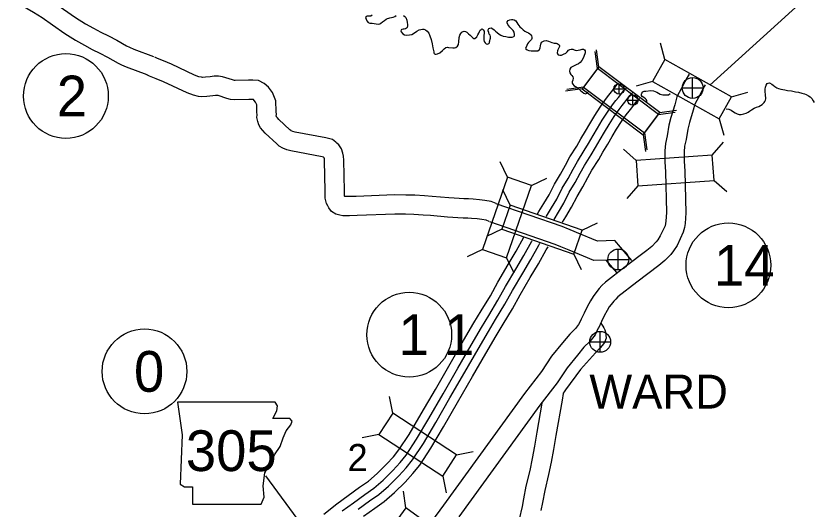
# Model space of a CAD drawing. Extents: x 1367863 to 1368197, y 380048 to 380261.
# Drawn here: x 1367891.07 to 1367912.71, y 380229.6 to 380242.97 of the extents above; entities that cross this region are included whole.
import ezdxf

# ---------------------------------------------------------------- set-up
doc = ezdxf.new("R2010")
doc.units = 0
for name, color, linetype in [('Level 10', 7, 'Continuous'), ('Level 15', 7, 'Continuous'), ('Level 2', 7, 'Continuous'), ('Level 20', 7, 'Continuous'), ('Level 21', 7, 'Continuous'), ('Level 26', 7, 'Continuous'), ('Level 27', 7, 'Continuous'), ('Level 30', 7, 'Continuous'), ('Level 6', 7, 'Continuous')]:
    doc.layers.add(name, color=color, linetype=linetype)

msp = doc.modelspace()

# ---------------------------------------------------------------- linework, layer by layer
at = {"layer": 'Level 10'}
for points in [[(1367891.032, 380243.854), (1367891.22, 380243.794), (1367891.456, 380243.711), (1367891.621, 380243.63), (1367891.816, 380243.521), (1367892.075, 380243.361), (1367892.365, 380243.153), (1367892.691, 380242.923), (1367892.954, 380242.757), (1367893.176, 380242.635), (1367893.378, 380242.527), (1367893.584, 380242.429), (1367893.807, 380242.311), (1367894.073, 380242.155), (1367894.149, 380242.124), (1367894.269, 380242.066), (1367894.803, 380241.868)], [(1367891.055, 380243.298), (1367891.254, 380243.229), (1367891.378, 380243.168), (1367891.551, 380243.071), (1367891.785, 380242.926), (1367892.062, 380242.728), (1367892.4, 380242.488), (1367892.689, 380242.307), (1367892.927, 380242.176), (1367893.142, 380242.061), (1367893.349, 380241.962), (1367893.553, 380241.854), (1367893.842, 380241.684), (1367893.938, 380241.646), (1367894.062, 380241.585), (1367894.621, 380241.378)], [(1367896.104, 380241.306), (1367896.03, 380241.321), (1367895.915, 380241.364), (1367895.289, 380241.659), (1367895.072, 380241.751), (1367894.912, 380241.811), (1367894.837, 380241.852)], [(1367896.024, 380240.789), (1367895.885, 380240.818), (1367895.713, 380240.881), (1367895.075, 380241.182), (1367894.878, 380241.266), (1367894.694, 380241.335), (1367894.587, 380241.393)], [(1367904.091, 380237.885), (1367903.96, 380237.935), (1367903.788, 380237.965), (1367903.64, 380237.985), (1367903.468, 380238.002), (1367903.34, 380238.009), (1367903.218, 380238.01), (1367903.087, 380238.017), (1367902.954, 380238.026), (1367902.811, 380238.037), (1367902.354, 380238.075), (1367902.15, 380238.092), (1367901.885, 380238.11), (1367901.646, 380238.114), (1367901.339, 380238.117), (1367900.301, 380238.077), (1367900.115, 380238.07), (1367900.022, 380238.071), (1367899.986, 380238.072), (1367899.979, 380238.084), (1367899.978, 380238.09), (1367899.979, 380238.228), (1367899.961, 380239.061), (1367899.957, 380239.164), (1367899.939, 380239.253), (1367899.903, 380239.366), (1367899.828, 380239.477), (1367899.776, 380239.52), (1367899.749, 380239.547), (1367899.652, 380239.623), (1367899.477, 380239.663), (1367898.64, 380239.821), (1367898.578, 380239.837), (1367898.539, 380239.853), (1367898.523, 380239.862), (1367898.498, 380239.885), (1367898.199, 380240.164), (1367898.16, 380240.205), (1367898.139, 380240.23), (1367898.134, 380240.245), (1367898.132, 380240.255), (1367898.134, 380240.299), (1367898.128, 380240.38), (1367898.121, 380240.671), (1367898.029, 380240.891), (1367897.923, 380241.035), (1367897.804, 380241.141), (1367897.652, 380241.215), (1367897.494, 380241.229), (1367897.377, 380241.227), (1367897.016, 380241.214), (1367896.995, 380241.216), (1367896.944, 380241.232), (1367896.669, 380241.321), (1367896.567, 380241.335), (1367896.444, 380241.338), (1367896.338, 380241.321), (1367896.209, 380241.306), (1367896.13, 380241.303), (1367896.104, 380241.306)], [(1367909.178, 380241.111), (1367909.257, 380241.253), (1367909.337, 380241.391)], [(1367909.176, 380241.108), (1367908.997, 380240.777), (1367908.935, 380240.563), (1367908.833, 380240.219), (1367908.779, 380240.007), (1367908.73, 380239.721), (1367908.684, 380239.511), (1367908.668, 380239.308), (1367908.668, 380239.017), (1367908.688, 380238.74), (1367908.712, 380237.64), (1367908.705, 380237.523), (1367908.698, 380237.403), (1367908.688, 380237.341), (1367908.672, 380237.275), (1367908.615, 380237.149), (1367908.544, 380237.006), (1367908.476, 380236.901), (1367908.432, 380236.843), (1367908.315, 380236.721), (1367908.181, 380236.611), (1367907.593, 380236.17), (1367907.055, 380235.749), (1367906.963, 380235.662), (1367906.89, 380235.583), (1367906.794, 380235.467), (1367906.723, 380235.367), (1367906.65, 380235.245), (1367906.562, 380235.08), (1367906.477, 380234.91), (1367906.393, 380234.732)], [(1367909.634, 380240.856), (1367909.711, 380240.994), (1367909.773, 380241.102)], [(1367909.635, 380240.86), (1367909.483, 380240.578), (1367909.437, 380240.417), (1367909.337, 380240.08), (1367909.29, 380239.898), (1367909.243, 380239.621), (1367909.202, 380239.434), (1367909.19, 380239.288), (1367909.19, 380239.035), (1367909.209, 380238.764), (1367909.235, 380237.629), (1367909.226, 380237.491), (1367909.218, 380237.345), (1367909.2, 380237.236), (1367909.168, 380237.105), (1367909.087, 380236.925), (1367908.998, 380236.747), (1367908.904, 380236.601), (1367908.829, 380236.503), (1367908.67, 380236.337), (1367908.503, 380236.2), (1367907.911, 380235.756), (1367907.397, 380235.353), (1367907.335, 380235.294), (1367907.282, 380235.238), (1367907.208, 380235.148), (1367907.161, 380235.081), (1367907.105, 380234.988), (1367907.026, 380234.839), (1367906.947, 380234.682), (1367906.866, 380234.51)], [(1367903.905, 380237.397), (1367903.82, 380237.429), (1367903.708, 380237.449), (1367903.581, 380237.466), (1367903.429, 380237.481), (1367903.324, 380237.487), (1367903.202, 380237.488), (1367903.054, 380237.496), (1367902.916, 380237.505), (1367902.77, 380237.517), (1367902.31, 380237.555), (1367902.11, 380237.571), (1367901.863, 380237.588), (1367901.639, 380237.592), (1367901.347, 380237.595), (1367900.321, 380237.555), (1367900.121, 380237.547), (1367900.015, 380237.549), (1367899.935, 380237.55), (1367899.853, 380237.566), (1367899.745, 380237.595), (1367899.627, 380237.671), (1367899.553, 380237.765), (1367899.529, 380237.818), (1367899.491, 380237.885), (1367899.455, 380238.028), (1367899.457, 380238.225), (1367899.439, 380239.045), (1367899.437, 380239.099), (1367899.432, 380239.121), (1367899.431, 380239.125), (1367899.416, 380239.141), (1367899.371, 380239.151), (1367898.524, 380239.311), (1367898.415, 380239.34), (1367898.311, 380239.381), (1367898.21, 380239.439), (1367898.143, 380239.502), (1367897.83, 380239.794), (1367897.768, 380239.859), (1367897.704, 380239.936), (1367897.66, 380240.017), (1367897.629, 380240.108), (1367897.608, 380240.213), (1367897.611, 380240.291), (1367897.606, 380240.356), (1367897.601, 380240.561), (1367897.572, 380240.631), (1367897.535, 380240.68), (1367897.51, 380240.703), (1367897.476, 380240.706), (1367897.391, 380240.705), (1367897.002, 380240.691), (1367896.893, 380240.701), (1367896.787, 380240.734), (1367896.551, 380240.81), (1367896.524, 380240.814), (1367896.48, 380240.815), (1367896.409, 380240.803), (1367896.249, 380240.785), (1367896.113, 380240.78), (1367896.024, 380240.789)], [(1367904.084, 380237.888), (1367905.873, 380237.268), (1367906.043, 380237.196)], [(1367903.913, 380237.394), (1367905.686, 380236.78), (1367905.839, 380236.715)], [(1367907.773, 380236.339), (1367907.31, 380236.878), (1367906.841, 380236.864), (1367906.275, 380237.103), (1367906.039, 380237.198)], [(1367907.364, 380236.014), (1367907.076, 380236.348), (1367906.742, 380236.339), (1367906.076, 380236.62), (1367905.843, 380236.714)], [(1367906.396, 380234.739), (1367906.33, 380234.607), (1367906.244, 380234.494), (1367906.09, 380234.341), (1367905.896, 380234.109), (1367905.597, 380233.744), (1367905.323, 380233.328), (1367904.862, 380232.735), (1367902.665, 380229.706), (1367902.338, 380229.27)], [(1367906.933, 380234.642), (1367906.953, 380234.611), (1367906.985, 380234.561), (1367907.011, 380234.516), (1367907.038, 380234.463), (1367907.062, 380234.399), (1367907.078, 380234.238), (1367907.034, 380234.115), (1367906.969, 380234.032), (1367906.912, 380233.97), (1367906.788, 380233.834), (1367906.383, 380233.387), (1367905.97, 380232.831), (1367905.937, 380232.778), (1367905.915, 380232.743), (1367905.911, 380232.734), (1367905.879, 380232.556), (1367905.708, 380231.596), (1367905.646, 380231.216), (1367905.581, 380230.873), (1367905.516, 380230.536), (1367905.413, 380230.108), (1367905.349, 380229.776), (1367905.305, 380229.565)], [(1367906.863, 380234.504), (1367906.775, 380234.329), (1367906.638, 380234.148), (1367906.475, 380233.987), (1367906.298, 380233.776), (1367906.019, 380233.434), (1367905.748, 380233.023), (1367905.28, 380232.421), (1367903.085, 380229.395)], [(1367905.334, 380232.473), (1367905.193, 380231.684), (1367905.132, 380231.308), (1367905.067, 380230.971), (1367905.005, 380230.646), (1367904.902, 380230.219), (1367904.837, 380229.878), (1367904.795, 380229.676), (1367904.716, 380229.327), (1367904.688, 380229.217), (1367904.676, 380229.171), (1367904.631, 380229.064), (1367904.57, 380228.946), (1367904.52, 380228.852), (1367904.475, 380228.756), (1367904.443, 380228.685), (1367904.397, 380228.557), (1367904.37, 380228.417), (1367904.366, 380228.259), (1367904.398, 380226.278)]]:
    msp.add_lwpolyline(points, dxfattribs=at)
at = {"layer": 'Level 15'}
for points in [[(1367907.222, 380240.909), (1367907.373, 380241.109), (1367907.413, 380241.148)], [(1367905.217, 380237.601), (1367905.255, 380237.667), (1367905.39, 380237.887), (1367905.529, 380238.118), (1367905.676, 380238.412), (1367905.838, 380238.682), (1367905.971, 380238.927), (1367906.092, 380239.147), (1367906.278, 380239.442), (1367906.39, 380239.634), (1367906.52, 380239.847), (1367906.632, 380240.045), (1367906.765, 380240.269), (1367906.912, 380240.497), (1367907.059, 380240.703), (1367907.151, 380240.821), (1367907.222, 380240.909)], [(1367907.411, 380240.761), (1367907.554, 380240.951), (1367907.615, 380241.012)], [(1367907.582, 380240.627), (1367907.718, 380240.808), (1367907.793, 380240.881)], [(1367905.454, 380237.533), (1367905.461, 380237.544), (1367905.595, 380237.763), (1367905.739, 380238.002), (1367905.886, 380238.297), (1367906.046, 380238.563), (1367906.181, 380238.812), (1367906.299, 380239.025), (1367906.483, 380239.318), (1367906.596, 380239.511), (1367906.727, 380239.726), (1367906.839, 380239.925), (1367906.969, 380240.143), (1367907.11, 380240.363), (1367907.251, 380240.559), (1367907.338, 380240.672), (1367907.411, 380240.761)], [(1367905.662, 380237.455), (1367905.781, 380237.65), (1367905.93, 380237.897), (1367906.077, 380238.192), (1367906.235, 380238.455), (1367906.372, 380238.707), (1367906.486, 380238.914), (1367906.669, 380239.205), (1367906.783, 380239.4), (1367906.914, 380239.616), (1367907.027, 380239.816), (1367907.154, 380240.029), (1367907.29, 380240.24), (1367907.426, 380240.429), (1367907.509, 380240.537), (1367907.582, 380240.627)], [(1367907.771, 380240.479), (1367907.899, 380240.65), (1367907.976, 380240.726)], [(1367905.896, 380237.38), (1367905.986, 380237.525), (1367906.14, 380237.782), (1367906.288, 380238.077), (1367906.443, 380238.337), (1367906.582, 380238.592), (1367906.692, 380238.792), (1367906.874, 380239.081), (1367906.988, 380239.277), (1367907.121, 380239.494), (1367907.235, 380239.696), (1367907.358, 380239.903), (1367907.488, 380240.105), (1367907.618, 380240.286), (1367907.696, 380240.388), (1367907.771, 380240.479)], [(1367899.422, 380229.461), (1367899.776, 380229.743), (1367900.085, 380229.968), (1367900.392, 380230.195), (1367900.631, 380230.363), (1367900.868, 380230.562), (1367901.121, 380230.817), (1367901.307, 380231.019), (1367901.457, 380231.204), (1367901.732, 380231.623), (1367902.062, 380232.181), (1367902.445, 380232.844), (1367902.849, 380233.54), (1367903.21, 380234.17), (1367903.491, 380234.65), (1367903.686, 380234.974), (1367903.936, 380235.381), (1367904.141, 380235.756), (1367904.42, 380236.231), (1367904.635, 380236.595), (1367904.845, 380236.968)], [(1367899.921, 380229.553), (1367900.227, 380229.775), (1367900.533, 380230.001), (1367900.777, 380230.173), (1367901.03, 380230.385), (1367901.295, 380230.651), (1367901.488, 380230.862), (1367901.651, 380231.063), (1367901.936, 380231.496), (1367902.269, 380232.06), (1367902.653, 380232.724), (1367903.056, 380233.421), (1367903.417, 380234.049), (1367903.697, 380234.527), (1367903.891, 380234.85), (1367904.143, 380235.261), (1367904.349, 380235.638), (1367904.626, 380236.109), (1367904.843, 380236.475), (1367905.06, 380236.863), (1367905.069, 380236.877)], [(1367900.355, 380229.599), (1367900.66, 380229.825), (1367900.91, 380230.001), (1367901.177, 380230.225), (1367901.452, 380230.501), (1367901.653, 380230.72), (1367901.827, 380230.934), (1367902.12, 380231.381), (1367902.457, 380231.951), (1367902.841, 380232.615), (1367903.245, 380233.312), (1367903.605, 380233.94), (1367903.884, 380234.416), (1367904.077, 380234.737), (1367904.331, 380235.152), (1367904.538, 380235.53), (1367904.814, 380235.998), (1367905.031, 380236.367), (1367905.248, 380236.752), (1367905.282, 380236.808)], [(1367900.497, 380229.406), (1367900.8, 380229.631), (1367901.056, 380229.811), (1367901.339, 380230.048), (1367901.625, 380230.335), (1367901.835, 380230.563), (1367902.021, 380230.793), (1367902.323, 380231.254), (1367902.664, 380231.83), (1367903.048, 380232.495), (1367903.452, 380233.193), (1367903.812, 380233.82), (1367904.09, 380234.294), (1367904.282, 380234.612), (1367904.538, 380235.032), (1367904.747, 380235.412), (1367905.02, 380235.877), (1367905.239, 380236.247), (1367905.454, 380236.631), (1367905.505, 380236.714)]]:
    msp.add_lwpolyline(points, dxfattribs=at)
at = {"layer": 'Level 2'}
for points in [[(1367900.731, 380242.989), (1367900.693, 380242.965), (1367900.657, 380242.959), (1367900.618, 380242.962), (1367900.592, 380242.966), (1367900.568, 380242.953), (1367900.555, 380242.927), (1367900.566, 380242.883), (1367900.587, 380242.839), (1367900.623, 380242.791), (1367900.666, 380242.776), (1367900.734, 380242.773), (1367900.784, 380242.76), (1367900.839, 380242.751), (1367900.894, 380242.744), (1367900.937, 380242.752), (1367900.969, 380242.775), (1367901.009, 380242.804), (1367901.065, 380242.844), (1367901.115, 380242.879), (1367901.151, 380242.897), (1367901.182, 380242.907), (1367901.213, 380242.916), (1367901.253, 380242.923), (1367901.299, 380242.936), (1367901.348, 380242.956), (1367901.38, 380242.977)], [(1367901.584, 380242.982), (1367901.616, 380242.957), (1367901.644, 380242.926), (1367901.674, 380242.857), (1367901.681, 380242.792), (1367901.688, 380242.737)], [(1367904.288, 380242.418), (1367904.354, 380242.408), (1367904.429, 380242.397), (1367904.492, 380242.394), (1367904.532, 380242.393), (1367904.57, 380242.41), (1367904.587, 380242.433), (1367904.594, 380242.468), (1367904.584, 380242.525), (1367904.557, 380242.574), (1367904.518, 380242.613), (1367904.468, 380242.66), (1367904.434, 380242.701), (1367904.41, 380242.739), (1367904.395, 380242.781), (1367904.392, 380242.812), (1367904.421, 380242.846), (1367904.461, 380242.864), (1367904.507, 380242.874), (1367904.546, 380242.872), (1367904.581, 380242.866), (1367904.623, 380242.837), (1367904.654, 380242.791), (1367904.685, 380242.746), (1367904.739, 380242.674), (1367904.78, 380242.634), (1367904.828, 380242.593), (1367904.874, 380242.557), (1367904.922, 380242.529), (1367904.969, 380242.506), (1367905.007, 380242.482), (1367905.035, 380242.453), (1367905.052, 380242.426), (1367905.061, 380242.39), (1367905.06, 380242.36), (1367905.051, 380242.333), (1367905.027, 380242.305), (1367905.003, 380242.28), (1367904.969, 380242.249), (1367904.944, 380242.212), (1367904.926, 380242.168), (1367904.905, 380242.122), (1367904.893, 380242.099), (1367904.899, 380242.074), (1367904.936, 380242.046), (1367904.983, 380242.033), (1367905.045, 380242.024), (1367905.083, 380242.018), (1367905.125, 380242.021), (1367905.167, 380242.019), (1367905.224, 380242.025), (1367905.268, 380242.062), (1367905.284, 380242.107), (1367905.292, 380242.156), (1367905.304, 380242.207), (1367905.321, 380242.253), (1367905.391, 380242.295), (1367905.454, 380242.299), (1367905.513, 380242.283), (1367905.557, 380242.263), (1367905.606, 380242.247), (1367905.664, 380242.234), (1367905.72, 380242.227), (1367905.748, 380242.219), (1367905.773, 380242.206), (1367905.798, 380242.187), (1367905.809, 380242.161), (1367905.807, 380242.139), (1367905.781, 380242.087), (1367905.764, 380242.052), (1367905.755, 380242.019), (1367905.749, 380241.97), (1367905.755, 380241.937), (1367905.778, 380241.916), (1367905.817, 380241.905), (1367905.869, 380241.908), (1367905.923, 380241.929), (1367905.981, 380241.962), (1367906.022, 380241.998), (1367906.057, 380242.041), (1367906.093, 380242.061), (1367906.13, 380242.065), (1367906.17, 380242.063), (1367906.21, 380242.045), (1367906.261, 380242.032), (1367906.315, 380242.039), (1367906.375, 380242.051), (1367906.422, 380242.068), (1367906.462, 380242.069), (1367906.489, 380242.05), (1367906.51, 380242.021), (1367906.508, 380241.969), (1367906.469, 380241.873), (1367906.451, 380241.822), (1367906.418, 380241.76), (1367906.376, 380241.707), (1367906.326, 380241.667), (1367906.264, 380241.639), (1367906.207, 380241.613), (1367906.156, 380241.593), (1367906.116, 380241.569)], [(1367901.688, 380242.737), (1367901.69, 380242.698), (1367901.683, 380242.658), (1367901.664, 380242.635), (1367901.638, 380242.62), (1367901.6, 380242.609), (1367901.569, 380242.606), (1367901.539, 380242.605), (1367901.517, 380242.589), (1367901.508, 380242.559), (1367901.515, 380242.535), (1367901.56, 380242.487), (1367901.606, 380242.459), (1367901.671, 380242.445), (1367901.74, 380242.452), (1367901.809, 380242.468), (1367901.878, 380242.508), (1367901.938, 380242.553), (1367902.005, 380242.59), (1367902.05, 380242.598), (1367902.093, 380242.608), (1367902.136, 380242.607), (1367902.175, 380242.587), (1367902.223, 380242.552), (1367902.265, 380242.499), (1367902.293, 380242.426), (1367902.33, 380242.331), (1367902.355, 380242.215), (1367902.379, 380242.104), (1367902.391, 380242.034), (1367902.399, 380241.993), (1367902.405, 380241.97), (1367902.416, 380241.951), (1367902.425, 380241.939), (1367902.443, 380241.931), (1367902.467, 380241.932), (1367902.505, 380241.943), (1367902.562, 380241.969), (1367902.639, 380242.03), (1367902.683, 380242.079), (1367902.727, 380242.115), (1367902.77, 380242.119), (1367902.802, 380242.11), (1367902.917, 380242.102), (1367902.962, 380242.107), (1367903, 380242.117), (1367903.045, 380242.151), (1367903.07, 380242.195), (1367903.078, 380242.267), (1367903.089, 380242.383), (1367903.11, 380242.448), (1367903.135, 380242.494), (1367903.167, 380242.528), (1367903.198, 380242.548), (1367903.228, 380242.551), (1367903.263, 380242.546), (1367903.299, 380242.531), (1367903.341, 380242.487), (1367903.387, 380242.447), (1367903.435, 380242.406), (1367903.465, 380242.377), (1367903.488, 380242.358), (1367903.513, 380242.361), (1367903.569, 380242.402), (1367903.601, 380242.456), (1367903.624, 380242.505), (1367903.639, 380242.542), (1367903.662, 380242.581), (1367903.684, 380242.603), (1367903.706, 380242.616), (1367903.722, 380242.611), (1367903.742, 380242.596), (1367903.764, 380242.551), (1367903.761, 380242.387), (1367903.763, 380242.322), (1367903.771, 380242.275), (1367903.791, 380242.237), (1367903.823, 380242.21), (1367903.861, 380242.206), (1367903.896, 380242.219), (1367903.913, 380242.242), (1367903.916, 380242.263), (1367903.918, 380242.289), (1367903.935, 380242.335), (1367903.941, 380242.363), (1367903.938, 380242.412), (1367903.927, 380242.449), (1367903.908, 380242.478), (1367903.892, 380242.521), (1367903.88, 380242.563), (1367903.879, 380242.594), (1367903.896, 380242.624), (1367903.92, 380242.64), (1367903.958, 380242.643), (1367904.004, 380242.618), (1367904.036, 380242.591), (1367904.077, 380242.556), (1367904.121, 380242.52), (1367904.175, 380242.476), (1367904.221, 380242.446), (1367904.288, 380242.418)], [(1367906.116, 380241.569), (1367906.088, 380241.526), (1367906.08, 380241.475), (1367906.09, 380241.429), (1367906.118, 380241.38), (1367906.145, 380241.351), (1367906.172, 380241.317), (1367906.179, 380241.281), (1367906.169, 380241.226), (1367906.158, 380241.184), (1367906.159, 380241.148), (1367906.17, 380241.115), (1367906.2, 380241.084), (1367906.243, 380241.054), (1367906.294, 380241.027), (1367906.337, 380240.99), (1367906.378, 380240.944), (1367906.422, 380240.907), (1367906.467, 380240.873), (1367906.514, 380240.86), (1367906.555, 380240.873), (1367906.583, 380240.9), (1367906.584, 380240.906)], [(1367910.576, 380240.339), (1367910.633, 380240.314), (1367910.684, 380240.298), (1367910.734, 380240.3), (1367910.814, 380240.316), (1367910.871, 380240.333), (1367910.924, 380240.357), (1367910.965, 380240.384), (1367911.015, 380240.419), (1367911.094, 380240.465), (1367911.15, 380240.497), (1367911.219, 380240.518), (1367911.264, 380240.537), (1367911.305, 380240.57), (1367911.336, 380240.593), (1367911.363, 380240.622), (1367911.381, 380240.65), (1367911.398, 380240.684), (1367911.407, 380240.721), (1367911.394, 380240.837), (1367911.387, 380240.911), (1367911.39, 380240.986), (1367911.399, 380241.04), (1367911.413, 380241.093), (1367911.442, 380241.134), (1367911.471, 380241.15), (1367911.508, 380241.151), (1367911.566, 380241.121), (1367911.605, 380241.094), (1367911.649, 380241.057), (1367911.706, 380241.024), (1367911.75, 380240.999), (1367911.813, 380240.981), (1367911.918, 380240.961), (1367911.991, 380240.949), (1367912.098, 380240.935), (1367912.215, 380240.913), (1367912.289, 380240.898), (1367912.383, 380240.876), (1367912.453, 380240.855), (1367912.501, 380240.839), (1367912.559, 380240.804), (1367912.607, 380240.773), (1367912.653, 380240.726), (1367912.688, 380240.671), (1367912.719, 380240.618)], [(1367908.179, 380240.637), (1367908.178, 380240.667), (1367908.167, 380240.694), (1367908.14, 380240.725), (1367908.096, 380240.754), (1367908.049, 380240.789), (1367908.031, 380240.815), (1367908.031, 380240.844), (1367908.042, 380240.878), (1367908.067, 380240.908), (1367908.109, 380240.925), (1367908.155, 380240.933), (1367908.289, 380240.951), (1367908.359, 380240.939), (1367908.452, 380240.899), (1367908.544, 380240.846), (1367908.616, 380240.834), (1367908.691, 380240.83), (1367908.765, 380240.834), (1367908.809, 380240.864)], [(1367910.332, 380240.451), (1367910.401, 380240.437), (1367910.465, 380240.413), (1367910.525, 380240.373), (1367910.576, 380240.339)]]:
    msp.add_lwpolyline(points, dxfattribs=at)
at = {"layer": 'Level 20'}
for p, q in [((1367908.671, 380241.789), (1367908.546, 380242.231)), ((1367906.841, 380241.545), (1367906.777, 380242)), ((1367906.878, 380241.592), (1367906.814, 380242.047)), ((1367908.335, 380241.187), (1367907.892, 380241.062)), ((1367906.426, 380240.994), (1367905.97, 380240.931)), ((1367906.463, 380241.041), (1367906.008, 380240.978)), ((1367910.477, 380240.78), (1367910.919, 380240.906)), ((1367908.53, 380240.347), (1367908.985, 380240.41)), ((1367908.492, 380240.3), (1367908.948, 380240.363)), ((1367910.14, 380240.178), (1367910.266, 380239.736)), ((1367908.115, 380239.796), (1367908.179, 380239.341)), ((1367908.077, 380239.749), (1367908.141, 380239.294)), ((1367907.891, 380239.052), (1367907.544, 380239.353)), ((1367909.954, 380239.197), (1367910.256, 380239.544)), ((1367904.399, 380238.597), (1367904.198, 380239.01)), ((1367905.051, 380238.371), (1367905.464, 380238.572)), ((1367910.002, 380238.509), (1367910.35, 380238.207)), ((1367904.473, 380237.839), (1367904.272, 380238.253)), ((1367907.939, 380238.364), (1367907.638, 380238.017)), ((1367904.248, 380237.188), (1367903.834, 380236.987)), ((1367906.428, 380237.163), (1367906.842, 380237.364)), ((1367903.722, 380236.642), (1367903.309, 380236.441)), ((1367904.374, 380236.416), (1367904.575, 380236.003)), ((1367906.202, 380236.511), (1367906.403, 380236.098)), ((1367901.293, 380232.204), (1367901.199, 380232.654)), ((1367900.914, 380231.627), (1367900.464, 380231.534)), ((1367903.022, 380231.069), (1367903.472, 380231.162)), ((1367902.644, 380230.492), (1367902.737, 380230.042)), ((1367901.648, 380229.636), (1367901.577, 380230.09))]:
    msp.add_line(p, q, dxfattribs=at)
for points in [[(1367910.477, 380240.78), (1367908.671, 380241.789), (1367908.335, 380241.187), (1367910.14, 380240.178)], [(1367908.492, 380240.3), (1367906.841, 380241.545), (1367906.426, 380240.994), (1367908.077, 380239.749)], [(1367908.53, 380240.347), (1367906.878, 380241.592), (1367906.463, 380241.041), (1367908.115, 380239.796)], [(1367907.939, 380238.364), (1367910.002, 380238.509), (1367909.954, 380239.197), (1367907.891, 380239.052)], [(1367904.374, 380236.416), (1367905.051, 380238.371), (1367904.399, 380238.597), (1367903.722, 380236.642)], [(1367904.248, 380237.188), (1367906.202, 380236.511), (1367906.428, 380237.163), (1367904.473, 380237.839)], [(1367900.914, 380231.627), (1367902.644, 380230.492), (1367903.022, 380231.069), (1367901.293, 380232.204)], [(1367903.319, 380228.417), (1367901.648, 380229.636), (1367901.242, 380229.079), (1367902.913, 380227.86)]]:
    msp.add_lwpolyline(points, close=True, dxfattribs=at)
at = {"layer": 'Level 21'}
msp.add_lwpolyline([(1367895.45, 380232.502), (1367895.582, 380231.618), (1367895.524, 380230.278), (1367895.641, 380230.204), (1367895.862, 380230.204), (1367895.862, 380229.733), (1367897.718, 380229.733), (1367897.807, 380229.924), (1367897.777, 380230.233), (1367897.821, 380230.587), (1367897.983, 380230.867), (1367898.086, 380231.073), (1367898.234, 380231.294), (1367898.322, 380231.53), (1367898.396, 380231.721), (1367898.528, 380231.883), (1367898.558, 380231.986), (1367898.499, 380232.06), (1367898.042, 380232.06), (1367898.145, 380232.266), (1367898.16, 380232.399), (1367898.099, 380232.5)], close=True, dxfattribs=at)
msp.add_lwpolyline([(1367897.837, 380230.505), (1367899.563, 380228.153), (1367898.747, 380226.66)], dxfattribs=at)
at = {"layer": 'Level 26'}
for p, q in [((1367909.422, 380240.733), (1367909.422, 380241.299)), ((1367907.427, 380240.849), (1367907.427, 380241.132)), ((1367907.286, 380240.991), (1367907.569, 380240.991)), ((1367909.139, 380241.016), (1367909.705, 380241.016)), ((1367907.658, 380240.689), (1367907.941, 380240.689)), ((1367907.8, 380240.547), (1367907.8, 380240.83)), ((1367907.404, 380236.085), (1367907.404, 380236.651)), ((1367907.121, 380236.368), (1367907.687, 380236.368)), ((1367906.915, 380233.852), (1367906.915, 380234.418)), ((1367906.633, 380234.135), (1367907.198, 380234.135))]:
    msp.add_line(p, q, dxfattribs=at)
for centre, radius in [((1367909.422, 380241.016), 0.283), ((1367907.427, 380240.991), 0.141), ((1367907.8, 380240.689), 0.141), ((1367907.404, 380236.368), 0.283), ((1367906.915, 380234.135), 0.283)]:
    msp.add_circle(centre, radius, dxfattribs=at)
at = {"layer": 'Level 27'}
for centre in [(1367892.426, 380240.798), (1367910.391, 380236.209), (1367901.736, 380234.329), (1367894.558, 380233.334)]:
    msp.add_circle(centre, 1.149, dxfattribs=at)
at = {"layer": 'Level 30'}
msp.add_line((1367909.89, 380241.092), (1367912.603, 380243.56), dxfattribs=at)

# ---------------------------------------------------------------- texts
at = {"layer": 'Level 20'}
msp.add_text('2', height=0.735, dxfattribs=at).set_placement((1367900.063, 380230.631))
at = {"layer": 'Level 21'}
msp.add_text('305', height=1.1032, dxfattribs=at).set_placement((1367895.679, 380230.633))
at = {"layer": 'Level 27'}
for s, height, p in [('2', 1.103, (1367892.179, 380240.247)), ('14', 1.1032, (1367910, 380235.658)), ('1 1', 1.1032, (1367901.448, 380233.778)), ('0', 1.103, (1367894.273, 380232.782))]:
    msp.add_text(s, height=height, dxfattribs=at).set_placement(p)
at = {"layer": 'Level 6'}
msp.add_text('WARD', height=0.9194, dxfattribs=at).set_placement((1367906.621, 380232.326))

doc.saveas('drawing.dxf')
